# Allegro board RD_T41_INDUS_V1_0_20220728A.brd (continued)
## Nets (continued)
BT_UART_CTS/PIR_PWR_EN_IOT: J14.7 R218.2 R220.2
BT_UART_RTS/LED_R_IOT: J14.6 R223.2 R225.2
BT_UART_RXD/USART2_TX_IOT: J14.8 R213.2 R215.2
BT_UART_TXD/USB_DET_IOT: J14.5 R187.2 R188.2
CHARG_DET_N_IOT: J14.4 R8.1 U1.9(STATS)
CLK_CTRL: R199.2 R200.1 U19.12(RXD[3]/CLK_CTL)
CODEC_AVDD: C61.1 C62.1 FB8.2 U7.R1(CODEC_AVDD)
CSI_CLKN_DVP_D4: R110.1 R124.1 TP26.1 U7.M2(CSI_CLKN_DVP_D4)
CSI_CLKP_DVP_D5: R108.1 R109.1 TP25.1 U7.L3(CSI_CLKP_DVP_D5)
CSI_DATAN0_DVP_D0: R102.1 R103.1 TP21.1 U7.L2(CSI_DATAN0_DVP_D0)
CSI_DATAN1_DVP_D2: R106.1 R107.1 TP24.1 U7.N1(CSI_DATAN1_DVP_D2)
CSI_DATAP0_DVP_D1: R100.1 R101.1 TP18.1 U7.L1(CSI_DATAP0_DVP_D1)
CSI_DATAP1_DVP_D3: R104.1 R105.1 TP23.1 U7.M3(CSI_DATAP1_DVP_D3)
CSI_VCC08: C146.1 C147.1 FB9.1 U7.N2(CSI_VCCA08)
CSI_VCC18: C144.1 C145.1 FB10.1 U7.K3(CSI_VCCA18)
DDR_VREF: C42.2 C43.1 R118.1 R119.2 U7.E5(DDR_VREF)
DDRPLL_VCCA: C133.1 C134.1 FB2.1 U7.B8(DDRPLL_VCCA)
DDRVDD: C37.1 C38.1 C39.1 C40.1 C41.1 C42.1 C44.1 C58.1 C129.1 C130.1 C131.1 C132.1 R30.1 R118.2 U7.E6(VDDMEM1) U7.E7(VDDMEM2) U7.E8(VDDMEM3) U7.E9(VDDMEM4) U7.E10(VDDMEM5) U7.E11(VDDMEM6) U7.E12(VDDMEM7) U7.F5(DDRVDD1) U7.F6(DDRVDD2) U7.F7(DDRVDD3) U7.F8(DDRVDD4) U7.F9(DDRVDD5) U7.F10(DDRVDD6) U7.F11(DDRVDD7) U7.F12(DDRVDD8)
DVP_3V3: J10.1 J10.2 R99.1
DVP_5V: J10.34 J10.35 J10.36 R127.1
DVP_D0: J10.11 R103.2
DVP_D1: J10.12 R101.2
DVP_D2: J10.13 R107.2
DVP_D3: J10.14 R105.2
DVP_D4: J10.16 R124.2
DVP_D5: J10.17 R109.2
DVP_D6: J10.18 U7.H2(SD0_DVP_D6_PA06)
DVP_D7: J10.19 U7.H3(SD1_DVP_D7_PA07)
DVP_D8: J10.21 U7.G1(SD2_DVP_D8_PA08)
DVP_D9: J10.22 U7.G2(SD3_DVP_D9_PA09)
DVP_D10: J10.23 U7.G3(SD4_DVP_D10_PA10)
DVP_D11: J10.24 U7.F2(SD5_DVP_D11_PA11)
DVP_HSYNC: J10.8 TP20.1 U7.J2(CS2_DVP_HSYNC_PA16)
DVP_MCLK_PA15: J10.28 R126.2 TP10.1
DVP_PCLK: J10.26 TP19.1 U7.F3(SA0_DVP_PCLK__PA14)
DVP_VSYNC: J10.9 TP22.1 U7.J3(RD_DVP_VSYNC_PA17)
EMMC_3V3: C87.1 C88.1 FB1.2 U11.E6(VCC_1) U11.F5(VCC_2) U11.J10(VCC_3) U11.K9(VCC_4)
EMMC_D4: R74.2 U11.B3(DAT4)
EMMC_D5: R75.2 U11.B4(DAT5)
EMMC_D6: R76.2 U11.B5(DAT6)
EMMC_D7: R77.2 U11.B6(DAT7)
EMMC_DS: TP33.1 U11.H5(DS)
EMMC_MSC0_CLK: C91.1 R86.2 U11.M6(CLK)
EMMC_MSC0_CMD: R78.2 R84.2 U11.M5(CMD)
EMMC_MSC0_D0: R70.2 R131.2 U11.A3(DAT0)
EMMC_MSC0_D1: R71.2 R133.2 U11.A4(DAT1)
EMMC_MSC0_D2: R72.2 R135.2 U11.A5(DAT2)
EMMC_MSC0_D3: R73.2 R137.2 U11.B2(DAT3)
EMMC_RST_PB21: C92.1 R79.1 U7.C17(MSC1_D2_TMS_PB21) U11.K5(RSTN)
EMMC_VDDI: C93.1 U11.C2(VDDI)
EXCLKI: C66.2 R41.2 U7.C1(EXCLK_XIN) Y1.1
EXCLKO: C67.2 R41.1 U7.D2(EXCLK_XOUT) Y1.3
GMAC_MDC: R177.2 U19.22(MDC)
GMAC_MDIO: R178.2 R189.2 U19.23(MDIO)
GMAC_NRST_PB28: C151.1 R207.2 U7.A11(DMIC_CLK_SMB2_SCK_PB28) U19.21(RESET_N)
GMAC_PHY_CLK: R175.2 U19.31(XTAL_IN)
GMAC_RXD0: R195.1 U7.U13(GMAC_RXD0_PWM6_PB15)
GMAC_RXD1: R192.2 R193.1 R198.1 U7.R12(GMAC_RXD1_PWM7_PB16)
GMAC_RXDV: R191.1 U7.U9(GMAC_RXDV_PWM3_PB09)
GMAC_TXCLK: R190.1 U7.T12(GMAC_TXCLK_PB06)
GMAC_TXD0: R179.2 U19.16(TXD[0])
GMAC_TXD1: R180.2 U19.17(TXD[1])
GMAC_TXEN: R176.2 U19.20(TXEN)
HPOUT: C76.2 U7.T1(HPOUTL)
I2C0_MIPI_DVP_SCK: J10.3 J11.20 TP29.1 U7.J4(SD7_SMB0_SCK_PA13)
I2C0_MIPI_DVP_SDA: J10.6 J11.19 TP28.1 U7.J1(SD6_SMB0_SDA_PA12)
I2C1_SCK_PB26: R46.2 R152.1 R184.1 U9.7(SCL) U21.6(SCL)
I2C1_SDA_PB25: R40.2 R140.1 R182.1 U9.8(SDA) U21.5(SDA)
IRLED_EN_N_PB19: C102.2 Q8.1(GATE) R165.1 U7.D16(MSC1_CMD_PB19)
KEY1_PB30: R89.1 SW1.2 U7.C12(DMIC_DAT1_UART4_RXD_PB30)
KEY_IOT_N: C95.2 D10.2(CATHODE) J9.18 R90.2 SW2.1
LDR0: C125.1 R92.1 R113.1 U7.P15(SADC_VIN0)
LED_G: R94.1 R181.1
LED_R_IOT: R95.1 R225.1
MCU_PWR: R8.2 R47.1 R54.1 R90.1 R93.1 R186.2
MICBIAS: C141.1 C142.1 R83.2 U7.P3(MICBIAS)
MICNL: C65.2 C78.1 D15.2(CATHODE) J7.1 R69.1
MICPL: C64.2 C78.2 D9.2(CATHODE) J7.2 R80.2
MIPI1_2LANE_3V3: J11.30 R129.2
MIPI1_2LANE_5V: J11.28 J11.29 R128.2
MIPI_DVP_IRCUTN_PB18: J10.31 J11.25 U7.E17(MSC1_D1_PB18)
MIPI_DVP_IRCUTP_PB17: J10.32 J11.24 U7.E16(MSC1_D0_PB17)
MIPI_DVP_MCLK: R38.1 R125.1 R126.1 TP27.1
MIPI_DVP_PWDN_PA19: J10.25 J11.26 R143.1 TP31.1
MIPI_DVP_RESET: J10.33 J11.18 TP30.1 U7.E3(SA2_PA18)
MIPI_MCLK_PA15: J11.22 R125.2 TP32.1
MIPI_RX_2LANE_CLKN0: J11.2 R110.2
MIPI_RX_2LANE_CLKP0: J11.3 R108.2
MIPI_RX_2LANE_DN0: J11.5 R102.2
MIPI_RX_2LANE_DN1: J11.8 R106.2
MIPI_RX_2LANE_DP0: J11.6 R100.2
MIPI_RX_2LANE_DP1: J11.9 R104.2
MSC0_CLK: R39.2 R85.1 R86.1
MSC0_CMD: R82.1 R84.1 U7.G17(MSC0_CMD_PB05)
MSC0_D0: R87.1 R131.1 U7.H16(MSC0_D0_PB00)
MSC0_D1: R132.1 R133.1 U7.J15(MSC0_D1_PB01)
MSC0_D2: R134.1 R135.1 U7.G15(MSC0_D2_PB02)
MSC0_D3: R136.1 R137.1 U7.G16(MSC0_D3_PB03)
NTC: R9.1 R11.2 TP3.1 U1.7(NTC)
OSC32_XI: C71.2 R52.2 U7.M16(OSC32_XI) Y3.2
OSC32_XO: C72.2 R52.1 U7.M15(OSC32_XO) Y3.1
OU_PWR_EN_PC18: D12.2 R233.1 U7.B5(SSI_SLV_DR_I2S_SDTI_PC18)
PHY_LED0: R202.2 R203.1 R211.2 U19.24(LED0/PHYAD[0])
PHY_LED1: R205.2 R206.1 R217.2 U19.25(LED1/PHYAD[1])
PIR_3V3: C123.1 C124.1 C127.1 C196.1 D18.1(ANODE) R227.2 R228.1 R258.2 R265.2 TP11.1 U15.5(VOUT) U24.4 U25.3(VDD)
PIR_H_IOT: J14.11 Q6.1(GATE) U24.1
PIR_IOT: R230.1 R257.2 U25.4(REL)
PIR_L_IOT: J14.13 Q7.1(GATE) U24.7
PIR_PWR_EN_IOT: C126.1 D18.2(CATHODE) R220.1 U15.3(EN)
PLL_AVDD18: C59.1 C60.1 FB3.1 U7.D3(PLL_AVDD)
POR_CTRL: R121.2 R122.2 U7.K16(POR_CTL)
PWR_ON_PC16: J14.2 U7.A3(SSI_SLV_CE0_I2S_DAC_LRCK_PC16)
PWRON: TP12.1 U7.K15(PWRON)
RMII_MDCK: R177.1 U7.R10(GMAC_MDCK_SMB2_SDA_PB10)
RMII_MDIO: R178.1 U7.T10(GMAC_MDIO_SMB2_SCK_PB11)
RMII_PHY_CLK: R175.1 U7.T9(GMAC_PHY_CLK_PB07)
RMII_TX0: R179.1 U7.R11(GMAC_TXD0_PWM4_PB13)
RMII_TX1: R180.1 U7.T11(GMAC_TXD1_PWM5_PB14)
RMII_TXEN: R176.1 U7.U11(GMAC_TXEN_PWM2_PB08)
RST_OUT: TP14.1 U7.J16(RST_OUT)
RTC_0V8: C99.1 C143.1 TP34.1 U7.L15(VDD_RTC) U13.5(VOUT)
RTC_1V8: C94.1 C98.1 C169.1 R97.2 R121.1 R142.1 TP36.1 U7.L17(VDDIO_RTC) U12.5(VOUT) U13.1(VIN)
RTC_IRQ_N_PB29: R153.1 U7.B12(DMIC_DAT0_UART4_TXD_PB29) U21.3(INT)
RX+: J13.3(CON_PIN[2]) U20.14(TX-/RX-)
RX-: J13.6(CON_PIN[5]) U20.16(TX+/RX+)
RX_N1: U19.6(TRXN1) U20.1(TD+/RD+)
RX_P1: U19.5(TRXP1) U20.3(TD-/RD-)
RXDV: R196.2 R197.1 U19.8(RXDV)
SD0_CD_N_PB27: J6.9(CD) R88.1 U7.B11(DRV_VBUS_SMB2_SDA_PB27)
SD0_MSC0_CLK: J6.5(CLK) R85.2
SD0_MSC0_CMD: J6.3(CMD) R61.2 R82.2
SD0_MSC0_D0: J6.7(DAT0) R62.2 R87.2
SD0_MSC0_D1: J6.8(DAT1) R63.2 R132.2
SD0_MSC0_D2: J6.1(DAT2) R64.2 R134.2
SD0_MSC0_D3: J6.2(DAT3) R65.2 R136.2
SD_PWR_EN_N_PB20: C82.2 Q3.1(GATE) R66.2 U7.E15(MSC1_CLK_TCK_PB20)
SENS1: C204.1 Q6.2(SOURCE) Q7.2(SOURCE) R265.1 R267.2 U25.2(SENS)
SFC1_CS_N: R123.1 U7.R7(SFC1_CE_PA29) U18.1(C\S\)
SFC1_SCLK: U7.T8(SFC1_CLK_PA22) U18.6(SCLK)
SFC1_SIO0: U7.R8(SFC1_DT_IO0_PA20) U18.5(SI/SIO0)
SFC1_SIO1: U7.T7(SFC1_DR_IO1_PA21) U18.2(SO/SIO1)
SFC1_SIO2: U7.U7(SFC1_WP_IO2_PA30) U18.3(W\P\/SIO2)
SFC1_SIO3: U7.R9(SFC1_HOLD_IO3_PA31) U18.7(R\E\S\E\T\/SIO3)
SFC_CS_N: R44.1 U7.T4(SFC0_CE_PA28) U8.1(C\S\)
SFC_SCLK: R43.1 U8.6(SCLK)
SFC_SIO0: U7.U5(SFC0_DT_IO0_PA23) U8.5(SI/SIO0)
SFC_SIO1: U7.R5(SFC0_DR_IO1_PA24) U8.2(SO/SIO1)
SFC_SIO2: U7.T5(SFC0_WP_IO2_PA26) U8.3(W\P\/SIO2)
SFC_SIO3: U7.T6(SFC0_HOLD_IO3_PA25) U8.7(R\E\S\E\T\/SIO3)
SLCD_BLEN: R183.1 R212.1 U23.15(EN1) U23.16(EN2)
SLCD_BT656_D0: R130.1 R144.1 U7.A15(SLCD_D0_UART3_TXD_PD00)
SLCD_BT656_D1: R145.1 R146.1 U7.B15(SLCD_D1_UART3_RXD_PD01)
SLCD_BT656_D2: R149.1 R150.1 U7.A16(SLCD_D2_UART4_TXD_PD02)
SLCD_BT656_D3: R154.1 R155.1 U7.C15(SLCD_D3_UART4_RXD_PD03)
SLCD_BT656_D4: R156.1 R158.1 U7.A17(SLCD_D4_UART5_TXD_PD04)
SLCD_BT656_D5: R160.1 R161.1 U7.B16(SLCD_D5_UART5_RXD_PD05)
SLCD_BT656_D6: R162.1 R163.1 U7.B17(SLCD_D6_SMB1_SDA_PD06)
SLCD_BT656_D7: R164.1 R166.1 U7.C16(SLCD_D7_SMB1_SCK_PD07)
SLCD_CS: R171.1 U7.B13(SLCD_CS_PWM5_PD10)
SLCD_CS_PD10: J15.7(CS) R171.2
SLCD_D0_PD00: J15.23(DB10) R130.2
SLCD_D1_PD01: J15.24(DB11) R145.2
SLCD_D2_PD02: J15.25(DB12) R149.2
SLCD_D3_PD03: J15.26(DB13) R154.2
SLCD_D4_PD04: J15.27(DB14) R156.2
SLCD_D5_PD05: J15.28(DB15) R160.2
SLCD_D6_PD06: J15.29(DB16) R162.2
SLCD_D7_PD07: J15.30(DB17) R164.2
SLCD_DC: R172.1 U7.C13(SLCD_DC_PWM6_PD11)
SLCD_DC_PD11: J15.8(RS) R172.2
SLCD_IOVDD: C105.1 C106.1 J15.32(IOVCC) R147.2
SLCD_LEDA: C185.2 J15.16(LED-A) U23.8(VOUT)
SLCD_LEDK: J15.17(LED1) J15.18(LED2) J15.19(LED3) J15.20(LED4) U23.4(D3) U23.5(D2) U23.6(D1)
SLCD_RDY: R174.1 U7.C14(SLCD_RDY_PWM7_PD12)
SLCD_RDY_PD12: J15.10(RD) R157.1 R174.2
SLCD_RST_PD09: J15.31(RESET) R170.2
SLCD_TE: R170.1 U7.A13(SLCD_TE_PWM4_PD09)
SLCD_VCI: C179.1 C180.1 J15.33(VCI) R148.2
SLCD_WR_BT656_PCLK: R168.1 R169.1 U7.B14(SLCD_WR_PD08)
SLCD_WR_PD08: J15.9(WR) R168.2
SOC_0V8: C46.1 C47.1 C48.1 C49.1 C50.1 C51.1 C52.1 C53.1 C54.1 C55.1 C56.1 C57.1 FB4.1 FB9.2 R31.1 U7.H5(VDD1) U7.H6(VDD2) U7.H7(VDD3) U7.H8(VDD4) U7.H9(VDD5) U7.H10(VDD6) U7.H11(VDD7) U7.H12(VDD8) U7.H13(VDD9) U7.J5(VDD10) U7.J13(VDD11) U7.K5(VDD12) U7.K13(VDD13) U7.L5(VDD14) U7.M5(VDD15) U7.M6(VDD16) U7.N6(VDD17) U7.N7(VDD18) U7.N8(VDD19) U7.N9(VDD20) U7.N10(VDD21)
SOC_1V8: C63.1 C174.1 C175.1 C176.1 C177.1 FB2.2 FB3.2 FB5.1 FB7.1 FB8.1 FB10.2 R20.1 R185.1 U7.K2(VDDIO18_2) U7.N11(VDDIO18_1)
SOC_3V3: C170.1 C171.1 FB6.1 J4.1 R19.1 R40.1 R42.2 R45.2 R46.1 R138.1 U7.J14(VDDIO1_2) U7.P9(VDDIO1_1)
SOC_BT_RST_N/PIR_IOT: J14.16 R229.2 R230.2
SOC_BT_RST_PC17: R229.1 U7.B3(SSI_SLV_DT_I2S_SDTO_PC17)
SOC_PWR_EN_IOT: D12.1 J9.17
SOC_WIFI_OOB_PC15: J14.1 U7.B4(SSI_SLV_CLK_I2S_DAC_BCLK_PC15)
SPEAK_EN: R58.1 U7.B10(GPIO_PB31) U10.1(/SD)
TEST_TE: TP16.1 U7.L13(TEST_TE)
TRST_: TP15.1 U7.D14(TRST_)
TX+: J13.1(CON_PIN[0]) U20.9(RX-/TX-)
TX-: J13.2(CON_PIN[1]) U20.11(RX+/TX+)
TX_N0: U19.4(TRXN0) U20.6(RD+/TD+)
TX_P0: U19.3(TRXP0) U20.8(RD-/TD-)
UART1_RXD: R42.1 R48.2 U7.F16(UART1_RXD_PB24)
UART1_TXD: R45.1 R51.2 U7.F15(UART1_TXD_PB23)
UART2_RXD_PC14: R215.1 U7.C7(I2S_ADC_LRCK_PC14)
UART2_TXD_PC13: J14.12 U7.B7(I2S_ADC_BCLK_PC13)
USB_AVD08: C135.1 C136.1 FB4.2 U7.R4(USB_AVD08)
USB_AVD18: C137.1 C138.1 FB5.2 U7.T3(USB_AVD18)
USB_AVD33: C139.1 C140.1 FB6.2 U7.R3(USB_AVD33)
USB_DET_IOT: C9.1 R10.1 R12.2 R188.1
USB_DM0: D2.2(CATHODE) J2.2(D-) U7.U1(USB0PN)
USB_DP0: D1.2(CATHODE) J2.3(D+) U7.T2(USB0PP)
USB_ID: R55.1 U7.U2(USB0ID)
USB_VBUS: R24.1 R27.1 U7.U3(VBUS)
VCM: C68.1 C69.1 U7.R2(VCM)
VOUT: C198.1 R255.1 R259.2 U16.2(VOUT)
WIFI_IO: C114.1 J14.17 R186.1
WIFI_MSC1_CLK_PC02: J9.10 U7.A1(MSC1_CLK_PC02)
WIFI_MSC1_CMD_PC03: J9.7 R246.2 U7.C3(MSC1_CMD_PC03)
WIFI_MSC1_D0_PC04: J9.11 R247.2 U7.B2(MSC1_D0_PC04)
WIFI_MSC1_D1_PC05: J9.14 R248.2 U7.A2(MSC1_D1_PC05)
WIFI_MSC1_D2_PC06: J9.5 R249.2 U7.C2(MSC1_D2_PC06)
WIFI_MSC1_D3_PC07: J9.6 R250.2 U7.B1(MSC1_D3_PC07)
WIFI_VBAT: C111.1 C112.1 C113.1 J9.1 J9.2 R13.1 TP4.1
WKUP: TP13.1 U7.J17(WKUP_PD31)
N6875993: D7.2(CATHODE) J5.1 U10.8(VO-)
N6876005: D6.2(CATHODE) J5.2 U10.5(VO+)
N6876073: C77.1 R56.1 R57.1 U10.6(VDD)
N6876131: R60.1 U10.4(-IN)
N6876183: C76.1 R60.2
N6876193: C75.1 R59.2
N7727802: D11.3 R95.2
N7727853: D11.2 R94.2
N16597671: R59.1 U10.3(+IN)
N16605475: R6.2 U1.11(ISET1)
N16605479: R7.2 U1.12(ISET2)
N16605539: L1.1 U1.3(SW_0) U1.4(SW_1)
N16605973: R4.1 R5.1 U1.13(USB_DET)
N16607200: J1.3 R1.2
N16626294: R15.1 U2.4(EN)
N16626314: C10.1 C11.1 R14.2 R15.2 U2.5(VIN)
N16626426: R16.1 R17.2 U2.3(FB)
N16626534: C28.1 C29.1 C34.1 L5.2 R30.2 R33.2 TP8.1 U5.6(OUT)
N16626558: C34.2 R33.1 R36.2 U5.1(FB)
N16626586: C24.2 R25.1 R28.2 U3.1(FB)
N16626718: L5.1 U5.4(SW)
N16626738: L3.1 U3.4(SW)
N16627048: C206.1 R32.2 U5.5(EN)
N16627266: L2.1 U2.1(SW)
N16627350: C96.1 R22.2 U3.5(EN)
N16676856: C25.2 R23.1 R29.2 U4.1(FB)
N16676932: L4.1 U4.4(SW)
N16677062: C205.1 R26.2 U4.5(EN)
N16732442: R43.2 U7.R6(SFC0_CLK_PA27)
N16973565: R116.2 U7.F13(DDR_ZQ)
N16973568: R117.2 U7.D9(RZQ)
N16979467: D4.2(CATHODE) J4.4 R51.1
N16979485: D5.2(CATHODE) J4.3 R48.1
N16981740: C64.1 U7.N3(MICPL)
N16981743: C65.1 U7.P2(MICNL)
N16981952: R120.2 U7.D4(EFUSE_AVDD)
N16985653: R38.2 U7.E1(SA1_DVP_MCLK_PA15)
N16990829: C85.1 R81.1 R83.1
N16990879: C79.2 R80.1 R81.2
N16990962: C79.1 R67.1 R69.2
N16994187: R142.2 U13.3(EN)
N16994244: C100.1 U13.4(BP/FB)
N16994305: C97.1 U12.4(BP/FB)
N16994361: R141.2 U12.3(EN)
N16994635: R143.2 U7.E2(WAIT_PA19)
N17002165: R191.2 U19.26(CRS/CRS_DV)
N17002179: R195.2 U19.9(RXD[0])
N17002181: R198.2 U19.10(RXD[1])
N17002261: R209.1 U19.30(NC)
N17002291: R204.2 U19.32(XTAL_OUT)
N17002321: R190.2 U19.15(TXC)
N17002359: C118.1 C119.1 U19.2(AVDDL_REG)
N17002395: C149.1 C150.1 U19.29(DVDDL_REG)
N17002469: R201.2 U19.28(RXER)
N17002544: R194.1 U19.1(PBIAS)
N17002574: C156.2 U20.7(CT2)
N17002587: D17.1 R221.2 U20.10(CT3) U20.13(MCT) U20.15(CT4)
N17002598: C155.2 U20.5(CT)
N17002608: C154.2 U20.2(CT1)
N17002683: J13.11(CON_PIN[10]) R211.1
N17002690: J13.13(CON_PIN[12]) R217.1
N17002738: C157.2 R221.1
N17006161: R98.1 R139.1 R246.1 R247.1 R248.1 R249.1 R250.1
N17009042: Q4.2(EMITTER) R92.2
N17009044: Q5.3(DRAIN) R113.2 R115.2
N17009046: Q5.1(GATE) R114.1
N17009089: C121.1 C122.1 R111.2 U15.1(VIN)
N17009287: Q6.3(DRAIN) R268.2
N17009319: Q7.3(DRAIN) R269.2
N17009402: C201.1 R258.1 R261.1 R262.2 U24.10
N17009422: R253.1 R261.2 R263.2
N17009484: C199.1 R255.2 U24.12
N17009506: C199.2 C200.1 R260.1 R264.2 U24.13
N17009512: C197.1 C200.2 R260.2 U24.14
N17009562: C202.1 R264.1
N17009566: C197.2 R256.2
N17009576: C195.1 R254.1 R256.1 U24.9
N17009610: C195.2 R254.2 R257.1 U24.3 U24.6 U24.8
N17009693: C203.1 R263.1 R266.2 U24.5
N17009695: C194.1 R227.1 R253.2 U24.2
N17009885: C188.1 C189.1 C190.1 C191.1 C192.1 C193.1 R252.2 U16.1(VCC)
N17009958: C128.1 C187.1 R228.2 R252.1
N17058437: R39.1 U7.H15(MSC0_CLK_PB04)
N17123098: C36.1 R49.1 U9.2(CELL)
N17123136: R53.1 U9.6(QSTRT)
N17123180: C45.1 R50.1 U9.3(VDD)
N17123378: R181.2 R182.2 U7.C11(SMB1_SDA_UART3_TXD_PB25)
N17123417: R183.2 R184.2 U7.C10(SMB1_SCK_UART3_RXD_PB26)
N17141430: C15.2 J3.1 Q1.1(GATE) Q2.3(COLLECTOR) R21.2
N17141450: D12.3 R231.2
N17141452: C15.1 Q1.2(SOURCE) R18.2 R21.1
N17141508: Q2.1(BASE) R231.1 R232.2
N17141576: D13.1(ANODE) R234.2
N17211450: C158.2 U21.1(OSCI) Y2.2
N17211478: C159.2 U21.2(OSC0) Y2.1
N17217380: C183.2 U23.10(C1+)
N17217382: C183.1 U23.11(C1-)
N17217384: C182.1 U23.12(C2-)
N17217386: C182.2 U23.9(C2+)
N17217517: R214.1 U23.1(ISET)
N17219479: C107.1 D14.1(ANODE) Q8.3(DRAIN) R167.1
N17219520: D14.2(CATHODE) D16.1(ANODE)
N17219530: D16.2(CATHODE) R159.1
N17242896: C32.1 C33.1 C35.1 L6.2 R31.2 R35.2 TP9.1 U14.6(OUT)
N17242898: C35.2 R35.1 R37.2 U14.1(FB)
N17242946: L6.1 U14.4(SW)
N17243021: C108.1 R34.2 U14.5(EN)
N17251040: R208.1 U6.4(EN)
N17251042: C164.1 C165.1 R173.2 R208.2 U6.5(VIN)
N17251086: R91.1 R96.1 U6.3(FB)
N17251195: L8.1 U6.1(SW)
N170100671: Q5.2(SOURCE) R226.2

Pads without a net: D11 1; J2 4; J10 4 5 30; J11 11 12 14 15 17; J13 4 5 7 8; J15 11 12 13 14 15 21; U2 2; U6 2; U7 A7 C8 L16 N15 P14 P16 R13 R14 R15 R16 R17 T13 T14 T15 T16 T17 U15 U16 U17; U9 9; U10 2; U11 A1 A2 A7 A8 A9 A10 A11 A12 A13 A14 B1 B7 B8 B9 B10 B11 B12 B13 B14 C1 C3 C5 C7 C8 C9 C10 C11 C12 C13 C14 D1 D2 D3 D4 D12 D13 D14 E1 E2 E3 E5 E8 E9 E10 E12 E13 E14 F1 F2 F3 F10 F12 F13 F14 G1 G2 G3 G10 G12 G13 G14 H1 H2 H3 H12 H13 H14 J1 J2 J3 J12 J13 J14 K1 K2 K3 K6 K7 K10 K12 K13 K14 L1 L2 L3 L12 L13 L14 M1 M2 M3 M7 M8 M9 M10 M11 M12 M13 M14 N1 N3 N6 N7 N8 N9 N10 N11 N12 N13 N14 P1 P2 P7 P8 P9 P10 P11 P12 P13 P14; U15 4; U19 11 13 18 19 27; U20 4 12; U21 7; U23 2 3

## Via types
v1: diameter 0.406, hole 0.203, TOP to BOTTOM, 1508 vias

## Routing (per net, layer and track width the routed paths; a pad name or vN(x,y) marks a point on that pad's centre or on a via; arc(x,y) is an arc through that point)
1V8: length 57
  TOP w0.254: v1(41.12,41.52) 43.57,41.52 43.87,41.22 45.29,41.22 46.68,39.83 R55.2 ; R139.2 68.01,46.78 v1(67.03,45.8)
  TOP w0.508: v1(32.64,42.85) 33.97,42.85 35.31,41.52 v1(41.12,41.52)
  BOTTOM w0.254: 32.59,41.88 32.59,41.41 32.41,41.22 28.34,41.22 C25.1 26.98,41.47 R23.2
  BOTTOM w0.381: v1(67.03,45.8) 63.56,45.8 62.35,47.01 45.64,47.01 41.12,42.49 v1(41.12,41.52)
3V3: length 147.7
  TOP w0.203: R205.1 v1(37.68,24.62)
  TOP w0.254: U8.8 33.57,28.73 C70.2 v1(33.58,28.06) ; R44.2 31.77,39.64 v1(31.69,39.56) ; v1(77.97,42.96) 80.4,42.96 81.91,44.47 99.49,44.47 R270.2 ; U19.14 v1(35.51,15.53) 35.72,15.32 R199.1 ; v1(68.94,47.75) R98.2 ; R207.1 v1(39.75,20.46) ; R157.2 v1(90.72,20.74) ; v1(75.59,35.68) R140.2 74.93,35.67 R153.2 ; v1(40.63,22.49) R202.1 R189.1 ; R271.2 v1(68.11,37.66) ; R89.2 86.17,30.11 ; R152.2 v1(73.85,35.1)
  TOP w0.381: R151.1 v1(90.16,28.12)
  TOP w0.508: Q4.1 82.72,90.43 80.49,90.43 C120.1 78.16,90.55 71.2,90.55 R112.2 69.43,89.3 60.03,79.9 32.38,79.9 ; v1(23.63,65.21) 15.42,73.42 R57.2
  BOTTOM w0.254: R123.2 31.49,34.08 ; v1(73.85,35.1) 73.85,37.21 ; R25.2 26.65,48.04 C24.1 27.99,47.72 31.62,47.72 31.92,48.02 ; 31.36,80.46 R165.2 32.2,79.73 C102.1 ; v1(75.59,35.68) 75.59,37.11
  BOTTOM w0.381: 57.98,7.99 60.12,5.85 FB1.1
  BOTTOM w0.508: v1(37.18,65.21) v1(23.63,65.21)
  vias: v1(32.34,48.55) v1(32.75,81.45) v1(32.71,80.57) v1(32.92,48.54) v1(37.12,58.5) v1(38,58.48) v1(40.17,48.99) v1(40.38,48.53) v1(78,40.92) v1(78.1,40.31) v1(88.03,30.45) v1(88.5,10.94) v1(88.95,30.44) v1(89.57,10.95)
AVDD33: length 0.7
  TOP w0.254: U19.7 v1(31.56,17.55)
GND: length 197
  TOP w0.081: 62.82,10.27 62.77,10.32 62.77,10.81 ; 63.27,10.88 63.27,10.32 63.22,10.27
  TOP w0.102: 51.1,29.53 51,29.64 ; 51.1,29.53 51.1,29.14 ; 51.1,29.53 51.1,29.64 ; 51,29.64 51.1,29.64 51.1,29.64 ; 51,29.64 51,29.64 ; v1(51.1,30.93) v1(51.1,30.28) 51.1,29.74 ; v1(51.1,30.93) v1(50.45,30.93) v1(50.45,30.28) 50.45,29.73 ; v1(51.1,30.93) 51.68,30.93 ; 50.35,29.64 50.38,29.64 ; 50.35,29.64 50.45,29.73 ; 50.35,29.64 49.95,29.64 ; 50.38,29.64 50.45,29.57 ; 50.38,29.64 50.52,29.64 ; 51,29.64 50.55,29.64 ; 51,29.64 51.1,29.74 ; 50.55,29.64 50.45,29.73 ; 50.55,29.64 50.52,29.64 ; 51.77,30.93 51.88,30.93 ; 51.77,30.93 51.77,31.02 ; 51.77,30.93 51.68,30.93 ; 51.88,30.93 52.25,30.93 ; 51.88,30.93 51.77,31.04 ; 51.1,29.74 51.1,29.64 ; 50.45,29.73 50.45,29.57 ; 51.77,31.04 51.77,31.48 ; 51.77,31.04 51.77,31.02 ; 50.51,31.57 51.7,31.57 ; 50.45,29.57 50.45,29.12 ; 50.45,29.57 50.52,29.64 ; 51.68,30.93 51.77,31.02
  TOP w0.203: C151.2 39.12,20.19 v1(39.12,20.45) ; v1(23.01,85.31) D9.1 v1(22.23,86) ; 64.52,7.07 64.47,7.07 64.09,6.69 v1(64.09,6.41) ; U7.K6 v1(54.35,36.13) U7.K7 ; v1(51.37,54.35) J11.10 v1(51.37,56.09) ; 23.11,79.85 C85.2 23.11,81.21 ; U11.J5 65.22,8.37 65.22,8.07 v1(65.23,8.06) ; U7.L6 v1(53.7,36.13) U7.L7 ; D5.1 v1(77.19,7.96) ; D5.1 v1(76.46,7.28) ; D5.1 77.19,6.73 v1(77.39,6.54) ; v1(80.56,7.96) D4.1 v1(81.29,7.28) ; U7.L8 v1(53.7,34.83) U7.L9 ; C9.2 88.27,54.15 R12.1 ; 65.53,6.07 65.76,5.83 v1(65.76,5.67) ; J11.7 v1(52.87,56.9) ; R204.1 v1(32.73,24.66) ; v1(18.86,85.93) D15.1 v1(18.07,85.31) ; v1(62.03,7.83) 62.29,7.83 U11.P6 62.54,8.07 63.02,8.55 63.02,8.57 ; v1(77.95,89.91) 77.95,89.72 C120.2 ; v1(67.41,7.33) 67.17,7.57 67.02,7.57 ; U7.J9 v1(55,34.83) U7.J8 ; R58.2 v1(9.45,75.83) ; v1(48.37,56.17) J11.16 v1(48.37,54.3) ; C95.1 v1(96.18,62.33) ; U7.J7 v1(55,36.13) U7.J6 ; U7.J10 v1(55,33.53) U7.J11 ; U7.N12 v1(52.4,32.22) U7.N13 ; U7.K10 v1(54.35,33.53) U7.K11 ; v1(65.86,8.14) 66.02,8.3 66.02,8.57 ; U7.K9 v1(54.35,34.83) U7.K8 ; U7.M13 v1(53.05,32.22) U7.M12 ; R272.1 65.37,34.92 v1(65.37,34.65) ; U7.C9 v1(59.55,34.83) ; U11.P4 v1(62.03,9.07) ; R206.2 v1(36.79,24.62) ; v1(92.48,45.53) 92.47,45.54 C114.2 91.18,45.54 v1(91,45.72) ; J11.1 v1(55.87,57.05) ; D10.1 v1(97.16,62.21) ; U11.C4 v1(67.52,8.57) ; U7.L10 v1(53.7,33.53) U7.L11 ; 63.27,10.88 63.04,11.11 v1(63.02,11.11) 62.77,10.87 62.77,10.81 ; 63.22,10.27 63.02,10.07 U11.N2 62.82,10.27 ; R200.2 R193.2 v1(33.86,15.31) ; J11.13 v1(49.87,57.03) ; R194.2 v1(31.68,24.68) ; J11.4 v1(54.37,56.14) ; R226.1 v1(69.94,86.69) ; U8.4 v1(29.76,36.18) ; C125.2 v1(78.15,87.34) ; R201.1 v1(34.3,24.02) ; R115.1 v1(75.71,87.35)
  TOP w0.254: v1(88.59,53.53) 88.27,53.85 R12.1 ; U7.G8 v1(56.95,35.48) U7.G7 ; U7.G9 v1(56.95,34.18) U7.G10 ; U7.G5 v1(56.95,36.78) U7.G6 ; U7.G12 v1(56.95,32.87) U7.G11 ; C70.1 v1(31.94,28.72) ; J4.2 v1(77.39,6.54) ; R203.2 v1(40.63,23.38) ; U7.N5 v1(52.4,37.43)
  TOP w0.305: U7.G13 56.63,31.9 v1(56.95,31.58) ; v1(45.87,58.88) J11.21 v1(45.87,56.98) ; v1(46.42,74.05) J10.20 v1(46.42,75.99) ; v1(44.87,56.98) J11.23 v1(44.87,58.88) ; J10.15 v1(43.92,73.29) ; v1(42.87,56.98) J11.27 v1(42.87,58.88) ; v1(50.92,71.35) J10.29 v1(50.92,73.29) ; v1(10.29,84.77) 10.14,84.61 U10.7 v1(10.14,82.46) ; v1(45.18,13.7) J6.6 v1(45.18,16.22) ; v1(49.92,73.29) J10.27 v1(49.92,71.35) ; v1(41.42,75.99) J10.10 v1(41.42,74.05) ; U7.P4 v1(52.4,37.43) ; J10.7 v1(39.92,73.29)
  TOP w0.33: v1(78.4,18.04) C98.2 77.82,17.83 v1(77.44,18.21) U13.2 75.78,19.87 v1(75.7,19.87) ; C99.2 v1(71.53,20.5)
  TOP w0.381: v1(19.01,80.79) R67.2 v1(18.29,81.43) ; R27.2 44.22,39.57 v1(43.96,39.3) ; v1(12.12,80.83) C77.2 v1(12.88,80.07)
  TOP w0.508: J13.14 14.71,10.75 14.71,8.28 ; J13.10 8.35,7.7 ; 12.59,28.57 12.59,24.3 J13.12 ; J13.9 8.35,28.49
  BOTTOM w0.203: v1(65.76,5.67) 65.76,5.49 C87.2 ; C13.2 v1(87.35,43.67) ; R120.1 59.51,40.29 v1(59.53,40.32) ; C80.2 v1(46.74,5.68) ; v1(24.28,43.59) 24.28,43.84 C20.2 23.55,43.89 v1(23.55,43.59) ; C198.2 v1(75.28,70.1) ; v1(53.56,27.83) 53.61,27.88 C143.2 ; C96.2 v1(28.56,52.98) ; U9.1 12.94,35.07 12.73,34.87 v1(12.73,34.59) ; v1(45.15,6.31) C81.2 v1(45.79,5.7) ; C127.2 v1(87.63,75.11) ; v1(67.03,9.08) 67.03,9.7 C93.2 ; C1.2 v1(8.94,64.31) ; C1.2 v1(10.2,64.31) ; C1.2 9.61,64.53 v1(9.26,64.89) ; R29.1 25.46,41.47 v1(25.25,41.68) ; C148.1 v1(34.67,27.99) ; v1(92.48,45.53) R17.1 v1(93.75,45.53) ; C202.2 v1(73.82,72.79) ; R232.1 12.08,70.13 v1(11.79,70.42) ; R266.1 v1(87.12,67.52) ; C89.2 63.11,11.02 v1(63.02,11.11) ; C205.2 v1(28.96,46.27) ; C201.2 v1(74.22,69.26) ; v1(13.79,36.91) 13.45,36.57 U9.4 12.64,36.57 v1(12.48,36.73) ; v1(98.99,42.01) 98.99,42.31 C10.2 98.26,42.32 v1(98.26,42.03) ; v1(33.42,44.8) C23.2 v1(32.8,45.37) ; C119.2 v1(32.24,21.86) ; v1(78.27,70.49) U24.11 v1(80.98,70.49) ; C6.2 v1(11.75,48.35) ; v1(96.76,38.45) 97.03,38.72 R91.2 v1(97.03,39.86) ; v1(67.41,7.33) 67.39,7.35 C88.2 ; U2.6 96.87,43.18 v1(96.96,43.09) 97.35,42.7 C11.2 ; R262.1 v1(74.22,68.3) ; C126.2 v1(98.61,71.44) ; C36.2 v1(11.34,34.41) ; v1(30.56,14.23) 30.56,14.55 R197.2 ; v1(24.91,43.68) C21.2 25.05,44.39 v1(25.7,44.39) U4.2 26.81,44.39 v1(27.1,44.11) ; v1(31.49,52.55) 31.49,52.11 C18.2 30.77,52.13 v1(30.77,52.83) ; v1(92.03,75.1) C204.2 92.61,75.1 R267.1 ; Q2.2 v1(9.96,69.63) ; C156.1 v1(28.51,21.46) ; C154.1 v1(28.5,15.1) ; v1(78.55,31.38) 78.7,31.24 U5.2 79.7,31.24 v1(79.97,31.51) ; v1(69.55,7.81) 69.19,7.45 C90.2 ; C203.2 v1(87.05,68.93) ; C91.2 v1(66.13,11.06) ; R269.1 v1(96.02,66.03) ; R36.1 v1(80.2,34.15) ; v1(25.31,50.98) U3.2 26.41,50.98 v1(26.57,50.82) ; v1(32.74,51.89) C19.2 v1(32.21,52.46) ; v1(62.03,7.83) 62.73,7.14 C92.2 ; v1(10.63,45.48) 10.81,45.3 C8.2 v1(12.12,45.3) 12.06,45.36 12.06,46.03 C7.2 ; v1(32.05,45.91) 32.05,45.4 C22.2 31.23,45.57 v1(31.23,45.91) ; C12.2 v1(87.24,42.59) ; C122.2 v1(95.46,68.8) ; C155.1 v1(28.54,18.92) ; C14.2 v1(87.24,41.45) ; C121.2 v1(95.46,69.69) ; C45.2 v1(11.98,37.82) ; R259.1 v1(73.28,70.1) ; R233.2 19.69,71.29
  BOTTOM w0.246: C7.2 v1(10.95,46.34) ; C6.2 v1(10.94,47.61)
  BOTTOM w0.254: R5.2 v1(10.29,41.07) ; R7.1 v1(12.84,39.14) ; R53.2 v1(18.92,36.07) ; C194.2 v1(89.25,72.66) ; R6.1 v1(15.01,39.14)
  BOTTOM w0.305: v1(96.13,72.62) U15.2 v1(96.13,70.35) ; D8.1 45.69,15.7 v1(45.18,16.22) ; C83.2 45.18,13.47 v1(45.18,13.7) 45.52,14.04 C84.2 ; v1(49.6,12.99) R68.2 v1(48.98,12.28)
  BOTTOM w0.33: 77.32,15.75 U12.2 75.05,15.75 v1(74.73,15.43)
  BOTTOM w0.508: J13.14 14.06,7.5 ; J13.9 8.35,28.3 ; J13.12 12.62,24.27 12.62,28.42 ; J13.10 8.35,8.39
  vias: v1(0.81,85.98) v1(0.81,80.9) v1(0.81,75.82) v1(0.81,70.74) v1(0.81,65.66) v1(0.81,60.58) v1(0.81,55.5) v1(0.81,50.42) v1(0.81,45.34) v1(0.81,40.26) v1(0.81,35.18) v1(0.81,30.1) v1(0.86,8.07) v1(1.52,34.54) v1(1.67,48.62) v1(1.68,44.92) v1(1.76,35.55) v1(1.71,33.59) v1(2.86,35.72) v1(2.89,48.7) v1(2.97,33.36) v1(3.1,44.7) v1(3.33,41.49) v1(3.59,47.51) v1(3.6,46.38) v1(3.63,45.28) v1(4.14,35.38) v1(4.16,33.97) v1(4.34,63.62) v1(4.46,28.4) v1(5.13,64.42) v1(5.23,37.69) v1(5.66,54.18) v1(5.86,45.33) v1(5.89,85.98) v1(5.89,80.9) v1(5.89,75.82) v1(5.89,70.74) v1(5.93,63.62) v1(5.94,8.07) v1(6.05,50.96) v1(6.15,91.03) v1(6.1,67.69) v1(6.07,46.37) v1(6.21,66.29) v1(6.27,0.73) v1(6.46,44.83) v1(6.75,51.72) v1(6.99,47.68) v1(7.02,36.38) v1(7.26,68.47) v1(7.23,32.2) v1(7.42,56.94) v1(7.58,65.96) v1(7.73,85.4) v1(8,52.45) v1(8.47,86.13) v1(8.48,84.84) v1(8.47,4.13) v1(8.72,45.63) v1(8.7,37.73) v1(8.79,80.6) v1(8.89,82.28) v1(9.01,52.16) v1(9.15,41.57) v1(9.24,35.05) v1(9.3,47.64) v1(9.33,46.42) v1(9.54,90.04) v1(9.54,28.4) v1(10.31,91.15) v1(10.46,85.44) v1(10.5,81.09) v1(10.56,54.02) v1(10.76,65.82) v1(10.81,38.71) v1(11.02,8.07) v1(11.32,32.34) v1(11.35,0.73) v1(11.61,41.74) v1(11.92,60.59) v1(12.19,82.66) v1(12.37,86.16) v1(12.38,84.88) v1(12.44,76.51) v1(12.72,69.33) v1(12.68,62.5) v1(12.87,89.89) v1(12.89,77.99) v1(13.06,85.45) v1(13.09,73.49) v1(13.1,41.55) v1(13.53,52.47) v1(13.55,4.13) v1(13.75,63.84) v1(14.05,42.53) v1(14.18,43.56) v1(14.51,66.2) v1(14.5,50.05) v1(14.58,47.89) v1(14.62,43.09) v1(14.62,28.4) v1(14.75,87.22) v1(14.69,83.07) v1(15.05,42.6) v1(15.13,63.65) v1(15.19,43.66) v1(15.3,39.85) v1(15.66,72.33) v1(15.9,66.24) v1(15.94,44.68) v1(16.04,41.82) v1(16.08,69.7) v1(16.34,61.23) v1(16.35,37.27) v1(16.43,0.73) v1(16.51,33.91) v1(16.55,32.38) v1(16.75,7.94) v1(16.97,91.19) v1(17.11,41.43) v1(17.17,66.32) v1(17.36,78.74) v1(17.36,73.66) v1(17.48,63.09) v1(17.65,3.21) v1(17.65,1.79) v1(17.71,46.43) v1(17.89,84.53) v1(17.95,65.73) v1(18.16,87.2) v1(18.1,10.53) v1(18.3,88.69) v1(18.36,37.79) v1(18.5,46.42) v1(18.68,66.29) v1(18.76,27.19) v1(18.92,87.32) v1(18.97,41.57) v1(19.04,1.23) v1(19.34,84.28) v1(19.44,60.62) v1(19.46,44.65) v1(19.65,25.48) v1(19.77,85.99) v1(19.83,47.73) v1(20,42.61) v1(20,35.76) v1(20.36,49.55) v1(20.44,53.94) v1(20.54,88.52) v1(20.6,46.41) v1(20.86,37.85) v1(21.08,1.23) v1(21.2,42.4) v1(21.5,85.93) v1(21.48,81.55) v1(21.51,0.73) v1(21.74,66.25) v1(21.8,84.25) v1(21.85,41.3) v1(21.94,43.56) v1(21.95,30.25) v1(22.05,35.34) v1(22.06,1.93) v1(22.11,87.29) v1(22.12,44.72) v1(22.16,3.5) v1(22.2,88.54) v1(22.57,91.02) v1(22.85,79.86) v1(22.77,5.77) v1(22.88,81.47) v1(22.93,25.74) v1(23.06,40.2) v1(23.37,4.42) v1(23.5,42.38) v1(23.67,50.16) v1(23.8,72.62) v1(23.84,70.32) v1(23.83,65.95) v1(23.89,39.61) v1(24.02,48.81) v1(24.36,83.38) v1(24.75,50.22) v1(24.77,4.38) v1(24.94,48.18) v1(25.04,77.69) v1(25.16,40.9) v1(25.18,5.71) v1(25.44,72.39) v1(25.56,36.19) v1(25.54,32.05) v1(25.66,39.4) v1(25.62,28.37) v1(25.69,66.03) v1(25.74,53.66) v1(25.84,56.32) v1(25.84,11.29) v1(26.16,69.89) v1(26.09,24.54) v1(26.61,49.77) v1(26.59,0.73) v1(26.88,84.03) v1(26.88,78.95) v1(26.88,58.33) v1(27.43,88.26) v1(27.55,74.94) v1(27.52,65.93) v1(27.67,81.87) v1(27.96,3.21) v1(28.06,72.69) v1(28.01,55.72) v1(28.11,38.74) v1(28.35,91.06) v1(28.31,82.45) v1(28.36,74.41) v1(28.56,8.15) v1(28.67,48.44) v1(28.67,22.78) v1(28.82,71.17) v1(28.91,25.68) v1(28.97,41.71) v1(29.16,66.17) v1(29.1,15.78) v1(29.29,20.75) v1(29.52,74.64) v1(29.64,87.46) v1(29.65,33.4) v1(29.92,72.62) v1(29.88,24.5) v1(29.92,12.37) v1(30.16,18.82) v1(30.31,21.95) v1(30.27,4.61) v1(30.41,58.68) v1(30.44,51.06) v1(30.72,39.57) v1(30.81,28.76) v1(31,17.04) v1(31.37,20.71) v1(31.42,18.8) v1(31.71,74.44) v1(31.67,0.73) v1(31.96,84.03) v1(32.13,35.86) v1(32.24,67.52) v1(32.23,53.8) v1(32.46,59.27) v1(32.85,36.56) v1(32.88,33.81) v1(33.06,34.59) v1(32.99,7.17) v1(33.24,33) v1(33.5,25.68) v1(33.65,76.24) v1(33.6,12.04) v1(33.76,19.8) v1(33.76,18.8) v1(33.95,68.98) v1(33.97,59.3) v1(34,36.21) v1(34.23,50.55) v1(34.31,23.05) v1(34.4,32.01) v1(34.4,6) v1(34.52,79.19) v1(34.56,17.97) v1(34.58,55.18) v1(34.76,19.8) v1(34.76,18.8) v1(34.96,56.76) v1(35.24,70.23) v1(35.35,51.65) v1(35.54,34.7) v1(35.6,57.62) v1(35.58,22.31) v1(35.71,91.15) v1(35.71,86.07) v1(35.76,80.87) v1(35.76,19.8) v1(35.76,18.8) v1(35.76,17.8) v1(35.67,10.17) v1(35.86,66.25) v1(35.79,32.92) v1(36.35,78.87) v1(36.55,28.71) v1(36.75,0.73) v1(36.86,36.03) v1(36.77,33.76) v1(37.01,12) v1(37.14,21.28) v1(37.21,52) v1(37.24,15.44) v1(37.28,34.38) v1(37.44,50.43) v1(37.66,54.06) v1(37.86,71.26) v1(37.94,68.95) v1(37.87,9.84) v1(38.13,16.6) v1(38.23,80.65) v1(38.24,38.41) v1(38.24,27.56) v1(38.2,13.07) v1(38.33,17.7) v1(38.54,73.7) v1(38.62,36.91) v1(38.62,34.17) v1(38.59,32.76) v1(38.71,46.23) v1(38.86,58.08) v1(39.16,29.95) v1(39.31,59.73) v1(39.36,55.14) v1(39.43,4.2) v1(39.56,26.34) v1(39.95,54.44) v1(40.79,91.15) v1(40.79,86.07) v1(40.79,52.88) v1(40.92,2.81) v1(41.04,46.01) v1(40.97,44.93) v1(41.07,50.24) v1(41.1,32.92) v1(41.19,27.73) v1(41.25,12.97) v1(41.3,30.35) v1(41.28,24.54) v1(41.28,19.29) v1(41.62,38.4) v1(41.62,36.9) v1(41.62,34.71) v1(41.7,83.14) v1(41.8,53.97) v1(41.8,6.09) v1(41.83,0.73) v1(42.01,47.54) v1(42.07,21.13) v1(42.23,31.24) v1(42.28,33.66) v1(42.34,16.29) v1(42.29,10.77) v1(42.64,61.01) v1(42.9,73.83) v1(42.87,63.44) v1(42.99,36.9) v1(43.06,13.54) v1(43.1,66.37) v1(43.23,77.44) v1(43.21,34.46) v1(43.52,32.45) v1(43.57,30.41) v1(43.54,16.26) v1(43.63,47.58) v1(43.68,49.98) v1(43.84,56.81) v1(43.97,12.49) v1(44.13,51.45) v1(44.71,53.38) v1(44.84,36.89) v1(44.84,24.29) v1(44.78,20.16) v1(44.91,73.74) v1(44.98,64.49) v1(45.24,60.41) v1(45.25,22.29) v1(45.38,62.76) v1(45.37,34.45) v1(45.54,36.91) v1(45.73,25.89) v1(45.8,33.72) v1(45.82,18.6) v1(45.87,91.15) v1(45.87,86.07) v1(45.88,19.66) v1(45.87,10.11) v1(46.01,11.17) v1(46.26,36.91) v1(46.23,34.44) v1(46.33,41.61) v1(46.3,33.18) v1(46.49,20.98) v1(46.68,40.64) v1(46.9,57.01) v1(46.87,56.13) v1(46.91,0.73) v1(47.02,22.18) v1(47.21,83.1) v1(47.18,50.07) v1(47.17,42.54) v1(47.26,40.67) v1(47.18,16.86) v1(47.31,53.66) v1(47.38,18.23) v1(47.44,8.63) v1(47.64,25.13) v1(47.68,28.03) v1(47.92,73.41) v1(47.9,3.09) v1(47.97,43.49) v1(48.31,77.44) v1(48.31,42.88) v1(48.41,41.15) v1(48.45,10.23) v1(48.5,60.61) v1(48.68,30.17) v1(48.92,74.09) v1(48.96,33.1) v1(48.93,30.87) v1(48.87,26.19) v1(49.09,23.14) v1(49.35,28.72) v1(49.38,59.35) v1(49.49,53.64) v1(49.57,49.99) v1(49.6,16.88) v1(50.14,16.29) v1(50.57,27.78) v1(50.6,19.64) v1(50.76,59.31) v1(50.69,8.83) v1(50.95,91.15) v1(50.95,86.07) v1(51.17,41.89) v1(51.37,69.03) v1(51.75,36.77) v1(51.94,50.05) v1(51.96,27.53) v1(51.97,53.22) v1(52.01,15.86) v1(51.99,0.73) v1(52.19,76.3) v1(52.32,42.87) v1(52.32,42.23) v1(52.31,41.6) v1(52.52,83.1) v1(52.84,73.42) v1(52.82,26.75) v1(52.9,23.14) v1(53.04,68.48) v1(52.98,19.8) v1(53.07,67.31) v1(53.31,71.41) v1(53.39,77.44) v1(53.41,59.35) v1(53.54,70.48) v1(53.63,66.53) v1(54.02,13.27) v1(54.26,49.84) v1(54.44,5.11) v1(54.58,53.43) v1(54.85,68.78) v1(54.79,41.25) v1(54.79,40.71) v1(54.79,40.15) v1(54.88,10.66) v1(55,30.28) v1(55.07,17.6) v1(55.18,2.56) v1(55.49,25.26) v1(55.64,18.13) v1(55.77,8.83) v1(56.03,91.15) v1(56.03,86.07) v1(56,21.82) v1(56.23,25.05) v1(56.24,19.63) v1(56.74,56.08) v1(56.96,75.08) v1(56.88,67.6) v1(56.95,59.2) v1(57.11,21.83) v1(57.07,0.73) v1(57.25,68.86) v1(57.24,12.79) v1(57.24,3.79) v1(57.57,83.14) v1(57.58,26.43) v1(57.71,42.44) v1(57.71,41.81) v1(57.77,49.08) v1(57.92,57.98) v1(57.91,14.79) v1(58.07,6.75) v1(58.31,73.39) v1(58.47,77.44) v1(58.55,69.8) v1(58.49,17.76) v1(58.75,48.97) v1(58.74,19.06) v1(58.68,15.14) v1(58.93,43.69) v1(58.96,41.23) v1(58.96,21.85) v1(58.98,7.89) v1(59.1,65.8) v1(59.14,46.07) v1(59.1,19.84) v1(59.26,41.92) v1(59.47,60.23) v1(59.72,66.49) v1(59.72,51.03) v1(59.84,3.24) v1(59.98,49) v1(59.99,22.23) v1(60.09,59.42) v1(60.23,69.49) v1(60.2,38.72) v1(60.37,16.48) v1(60.54,50.73) v1(60.53,14.9) v1(60.81,10.82) v1(60.92,67.22) v1(61.11,91.15) v1(61.11,86.07) v1(61.21,39.01) v1(61.45,33.07) v1(61.53,46.13) v1(61.64,41.62) v1(61.62,36.39) v1(61.77,41) v1(61.94,64.24) v1(61.91,50.74) v1(61.92,11.07) v1(62,53.3) v1(62.15,39.01) v1(62.16,4.33) v1(62.15,0.73) v1(62.2,83.3) v1(62.43,62.43) v1(62.5,36.78) v1(62.64,52.78) v1(62.62,33.07) v1(62.68,48.78) v1(62.86,44.91) v1(62.96,58.38) v1(62.94,13.84) v1(63.04,59.7) v1(62.98,31.74) v1(63.12,55.89) v1(63.22,36.37) v1(63.28,64.93) v1(63.44,19.49) v1(63.46,18.3) v1(63.57,52.58) v1(63.7,44.21) v1(63.71,42.93) v1(63.7,36.81) v1(63.7,13.29) v1(63.84,77.46) v1(63.79,66.51) v1(64.13,33.08) v1(64.36,83.31) v1(64.31,45.14) v1(64.31,31.59) v1(64.43,55.71) v1(64.37,51.24) v1(64.56,61.15) v1(64.65,59.01) v1(64.57,18.34) v1(64.65,9.06) v1(64.68,11.14) v1(64.93,13.33) v1(64.89,2.18) v1(65.06,21.87) v1(65.39,63.21) v1(65.41,33.08) v1(65.53,12.73) v1(65.61,18.36) v1(65.72,31.46) v1(65.77,39.31) v1(65.91,24.55) v1(65.99,84.93) v1(66.05,56.25) v1(66.1,12.26) v1(66.19,91.15) v1(66.25,87.17) v1(66.17,59.98) v1(66.35,33.98) v1(66.29,6.66) v1(66.38,20.34) v1(66.56,40.13) v1(66.51,28.12) v1(66.64,74.22) v1(66.61,70.87) v1(66.62,61.87) v1(66.75,11.3) v1(66.69,5.57) v1(66.91,53.28) v1(66.96,26.1) v1(66.9,24.55) v1(67.06,83.67) v1(66.98,23.03) v1(67.12,49.52) v1(67.17,51.84) v1(67.23,0.73) v1(67.27,28.13) v1(67.42,12.1) v1(67.46,5.57) v1(67.76,35.46) v1(67.86,77.54) v1(67.85,28.12) v1(67.93,62.54) v1(68.06,38.29) v1(68.1,41.63) v1(68.14,24.55) v1(68.08,12.74) v1(68.19,59.45) v1(68.29,21.89) v1(68.34,18.66) v1(68.41,32.67) v1(68.47,49.15) v1(68.48,28.14) v1(68.65,44.85) v1(68.69,13.34) v1(68.83,3.52) v1(68.88,16.11) v1(69.02,85.4) v1(69.13,36.5) v1(69.17,88.09) v1(69.2,71.76) v1(69.31,39.44) v1(69.43,42.96) v1(69.53,44.98) v1(69.62,38.37) v1(69.66,28.15) v1(69.59,13.51) v1(69.84,61.18) v1(69.83,19.51) v1(69.83,6.18) v1(69.87,49.16) v1(70.24,55.75) v1(70.34,53.23) v1(70.42,32.54) v1(70.51,59.41) v1(70.62,29.21) v1(70.61,8.23) v1(70.61,3.15) v1(70.71,34.34) v1(70.7,23.03) v1(70.79,24.55) v1(70.77,15.9) v1(71.27,91.15) v1(71.37,40.21) v1(71.37,36.58) v1(71.49,28.13) v1(71.62,75.66) v1(71.62,70.58) v1(71.69,41.99) v1(71.68,30.65) v1(71.81,80.77) v1(71.78,29.78) v1(72.04,88.33) v1(72.32,6.05) v1(72.31,0.73) v1(72.42,29.98) v1(72.49,42.98) v1(72.55,17.54) v1(72.85,36.32) v1(72.94,41.81) v1(72.9,12.28) v1(72.97,29.78) v1(73.16,22.02) v1(73.26,38.51) v1(73.21,19.66) v1(73.38,8.8) v1(73.49,34.61) v1(73.51,28.13) v1(73.57,29.08) v1(73.65,25.97) v1(73.76,56.64) v1(73.87,88.42) v1(73.87,42.98) v1(74.11,66.77) v1(74.1,5.97) v1(74.25,52.46) v1(74.33,40.19) v1(74.52,82.37) v1(74.58,59.9) v1(74.73,25.91) v1(74.86,42.04) v1(74.84,20.54) v1(74.89,78.92) v1(74.89,38.52) v1(74.96,10.32) v1(74.99,24.59) v1(75.1,73.96) v1(75.25,89.44) v1(75.17,59.27) v1(75.18,13.69) v1(75.34,28.13) v1(75.45,56.37) v1(75.46,49.6) v1(75.46,44.8) v1(75.55,25.91) v1(75.48,12.39) v1(75.8,77.57) v1(75.92,41.13) v1(76.01,70.33) v1(76.18,78.96) v1(76.35,91.15) v1(76.3,59.19) v1(76.37,76) v1(76.43,45.25) v1(76.37,42.9) v1(76.56,24.56) v1(76.61,35.52) v1(76.58,20.97) v1(76.76,25.91) v1(76.77,33.72) v1(76.93,55.27) v1(77.41,77.95) v1(77.43,28.15) v1(77.41,2.77) v1(77.39,0.73) v1(77.63,67.43) v1(77.6,57.43) v1(77.8,10.97) v1(77.88,76.26) v1(77.96,52.16) v1(77.93,20.87) v1(77.97,83.76) v1(78.04,78.94) v1(78.07,25.96) v1(78.98,65.41) v1(79.25,49.77) v1(79.59,75.37) v1(79.66,35.5) v1(79.63,15.16) v1(79.75,78.78) v1(79.76,19.42) v1(79.75,11.22) v1(80.18,73.16) v1(80.7,32.07) v1(80.68,27.06) v1(80.99,53.58) v1(81.05,51.7) v1(81.01,48.46) v1(81.09,35.28) v1(81.33,89.52) v1(81.31,87.42) v1(81.32,81.46) v1(81.43,91.15) v1(81.46,26.04) v1(81.53,67.37) v1(81.49,15.15) v1(81.58,60.23) v1(81.63,46.48) v1(81.72,32.17) v1(81.67,24.73) v1(81.8,17.26) v1(82.01,78.22) v1(81.99,12.18) v1(82.08,63.22) v1(82.23,70.72) v1(82.33,73.06) v1(82.42,31.53) v1(82.53,81.44) v1(82.53,4.83) v1(82.47,0.73) v1(82.65,8.87) v1(83.05,83.76) v1(83.15,58.95) v1(83.36,75.19) v1(83.44,72.13) v1(83.39,69.23) v1(84.06,65.41) v1(84.61,22.14) v1(84.75,24.82) v1(84.72,14.52) v1(84.81,67.83) v1(84.81,19.05) v1(84.78,16.93) v1(84.78,10.39) v1(85.26,3.29) v1(85.33,75.62) v1(85.41,80.46) v1(85.42,73.38) v1(85.44,54.9) v1(85.46,46.85) v1(85.5,57.31) v1(85.54,48.88) v1(85.74,60.18) v1(85.83,66.57) v1(85.81,8.78) v1(85.93,6.1) v1(86.03,51.61) v1(86.34,61.06) v1(86.43,58.98) v1(86.51,91.15) v1(86.58,87.63) v1(86.73,52.62) v1(86.89,32.75) v1(86.99,64.15) v1(87.17,35.57) v1(87.46,37.91) v1(87.55,2.31) v1(87.55,0.73) v1(87.7,70.32) v1(87.74,40.15) v1(87.67,25.97) v1(87.7,11.21) v1(87.68,7.86) v1(87.9,48.5) v1(87.9,27.53) v1(87.91,22.49) v1(88.13,83.76) v1(88.19,19.89) v1(88.21,14.19) v1(88.17,4.1) v1(88.27,18.68) v1(88.3,17.53) v1(88.28,16.46) v1(88.28,15.13) v1(88.33,12.78) v1(88.41,65.77) v1(88.37,40.66) v1(88.55,61.22) v1(88.52,34.33) v1(88.51,20.98) v1(88.59,80.41) v1(88.69,59.01) v1(88.96,27.94) v1(89.04,78.03) v1(88.99,29.06) v1(89.03,23.86) v1(89.19,31.58) v1(89.33,88.36) v1(89.39,76.27) v1(89.43,6.2) v1(89.51,70.6) v1(89.61,68.54) v1(89.88,56.53) v1(89.87,52.76) v1(89.94,21.04) v1(90.07,35.69) v1(90.24,63.44) v1(90.18,24.71) v1(90.31,7.87) v1(90.76,75.25) v1(90.78,72.95) v1(90.92,77.79) v1(90.89,11.04) v1(91.03,35.66) v1(91.13,61.28) v1(91.15,33.11) v1(91.29,2.43) v1(91.38,66.9) v1(91.59,91.15) v1(91.58,71.79) v1(91.78,69.21) v1(91.8,35.62) v1(91.97,40.24) v1(92.07,42.9) v1(92.16,7.49) v1(92.08,3.29) v1(92.22,63.52) v1(92.32,55.66) v1(92.35,54.57) v1(92.3,53.34) v1(92.34,51.94) v1(92.32,50.11) v1(92.3,32.54) v1(92.31,29.7) v1(92.27,27.97) v1(92.43,57.22) v1(92.49,47.8) v1(92.62,48.8) v1(92.63,0.73) v1(92.68,80.27) v1(92.73,39.66) v1(92.82,70.79) v1(92.78,35.62) v1(92.88,77.96) v1(92.88,16.53) v1(92.91,15.24) v1(93,58.55) v1(93.03,21.66) v1(92.98,19.81) v1(93.01,18.62) v1(92.97,17.51) v1(93.12,27.97) v1(93.07,14.31) v1(93.07,13.17) v1(93.21,83.76) v1(93.23,30.98) v1(93.19,7.47) v1(93.36,51.81) v1(93.27,11.47) v1(93.39,60.38) v1(93.39,43.87) v1(93.5,50.08) v1(93.65,63.75) v1(93.61,40.06) v1(93.86,8.11) v1(93.96,40.6) v1(94.16,65.32) v1(94.18,27.61) v1(94.26,18.81) v1(94.27,72.28) v1(94.41,88.36) v1(94.57,73.51) v1(94.7,69.42) v1(94.69,62.49) v1(94.73,33.63) v1(94.71,26.74) v1(94.72,22.35) v1(94.9,41.17) v1(94.95,20.13) v1(94.95,19.12) v1(94.95,18.13) v1(94.91,11.59) v1(94.94,10.37) v1(95.21,45.44) v1(95.26,43.83) v1(95.43,77.27) v1(95.56,76.27) v1(95.65,29.29) v1(96.01,82.02) v1(96.03,3.73) v1(96.26,42.1) v1(96.18,9.79) v1(96.36,6.65) v1(96.43,58.43) v1(96.55,55.85) v1(96.61,53.12) v1(96.67,91.15) v1(96.9,47.51) v1(97.03,65) v1(97.23,38.12) v1(97.21,37.07) v1(97.23,35.91) v1(97.46,58.55) v1(97.47,52.34) v1(97.49,27.28) v1(97.52,24.39) v1(97.55,23.4) v1(97.53,12.03) v1(97.48,8.98) v1(97.59,10.65) v1(97.76,30.8) v1(97.75,28.44) v1(97.69,17.9) v1(97.71,0.73) v1(97.83,26.01) v1(97.77,15.34) v1(98.01,50.88) v1(98.01,45.89) v1(98.04,23.88) v1(98.33,60.84) v1(98.33,59.11) v1(98.52,24.33) v1(98.53,23.38) v1(98.7,79.45) v1(98.7,76.34) v1(98.74,65.4) v1(98.77,35.74) v1(98.97,55.67) v1(99.09,85.32) v1(99.19,68.99) v1(99.28,49.96) v1(99.32,31.7) v1(99.27,28.87) v1(99.3,14.41) v1(99.37,58.35) v1(99.46,57.01) v1(99.38,33.77) v1(99.45,25.25) v1(99.38,22.58) v1(99.57,54.42) v1(99.65,7.6) v1(99.76,64.2) v1(99.72,51.87) v1(99.72,45.23) v1(99.94,35.48) v1(100.08,25.95) v1(100.35,23.99) v1(100.52,26.65) v1(100.69,19.49) v1(100.79,11.4) v1(100.94,8.9) v1(101.03,29.97) v1(101.31,35.94) v1(101.56,38.76) v1(102.02,85.9) v1(102.05,81.95) v1(102.05,76.87) v1(102.05,71.79) v1(102.05,66.71) v1(102.05,61.63) v1(102.05,56.55) v1(102.05,51.47) v1(102.05,46.39) v1(102.05,41.31) v1(102.05,36.23) v1(102.05,31.15) v1(102.05,26.07) v1(102.05,20.99) v1(102.05,15.91) v1(102.05,10.83) v1(102.05,5.75)
VBAT2: length 89.5
  TOP w0.254: v1(76.53,45.78) 80.76,50 89.42,50 R2.2 ; v1(41.09,44.36) 41.09,44.37 27.68,44.37 27.12,44.92 25.46,44.92 24.7,44.16 v1(12.4,44.16)
  BOTTOM w0.254: v1(41.09,44.36) 44.68,47.96 63.2,47.96 64.28,46.87 75.44,46.87 v1(76.53,45.78) ; 4.23,37 9.38,37 R50.2 R49.2
VCC_3V3: length 75.2
  TOP w0.254: R234.1 87.13,9.55 v1(87.09,9.59)
  TOP w0.381: v1(82.25,35.55) 82.25,37.93 80.41,39.76 C181.1 76.15,38.85 U21.8
  TOP w0.457: v1(78.69,15.81) 78.69,16.24 R97.1
  L3_PWR w0.381: v1(87.94,34.9) 82.9,34.9 v1(82.25,35.55)
  BOTTOM w0.203: R96.2 92.07,39.17 91.66,38.76
  BOTTOM w0.508: U12.1 77.8,16.7 C86.1 v1(78.69,15.81) 78.69,14.77 R141.1 78.66,13.68 82.75,9.59 v1(87.09,9.59) 90.26,9.59 91.66,10.99 91.66,30.1 87.94,33.82 v1(87.94,34.9) 87.94,36.47 89.11,37.64
VCC_5V: length 140
  TOP w0.254: R10.2 80.71,54.15 70.14,43.58 v1(70.06,43.58)
  TOP w0.305: R24.2 v1(42.83,38.68)
  TOP w0.508: v1(14.17,45.59) 13.78,45.98 11.98,45.98 10.96,44.96 10.96,40.85 v1(10.29,40.18) 13.54,40.18 16.57,43.21 v1(19.61,43.21) ; v1(26.36,40.06) 29.94,40.06 30.56,40.68 33.45,40.68 35.15,38.98 42.53,38.98 v1(42.83,38.68)
  L3_PWR w0.508: v1(70.06,43.58) 80.41,43.58 89.18,34.82 v1(89.18,33.68)
  BOTTOM w0.254: 97.29,25.75 U23.13 ; R4.2 v1(10.29,40.18) ; R9.2 v1(19.61,43.21)
  BOTTOM w0.432: 97.29,25.75 97.29,26.27 C184.2
  BOTTOM w0.508: v1(89.18,33.68) 96.2,26.66 C184.2 ; v1(19.61,43.21) 21.31,43.21 24.46,40.06 v1(26.36,40.06) ; v1(70.06,43.58) 63.14,43.58 61.21,45.51 58.17,45.51 57.71,45.96 46.39,45.96 42.21,41.78 42.21,40.59 42.83,39.96 v1(42.83,38.68)
  vias: v1(8.72,49.45) v1(9.41,49.04) v1(10.27,49.03) v1(11.03,49.02)
VCC_IN: length 2.5
  BOTTOM w0.254: v1(11.94,43.33) v1(12.48,43.33) U1.15 ; v1(12.95,45.09) v1(13.49,45.09) 13.87,44.71 U1.1
  vias: v1(17.78,50.86) v1(17.8,49.84) v1(18.96,50.82) v1(19,49.86)
VCC_SOC: length 22.3
  TOP w0.254: v1(60.73,70.73) 60.13,70.73 R127.2 60.35,71.5 v1(60.65,71.5)
  TOP w0.508: v1(23.03,64.01) 14.15,72.9 R56.2
  vias: v1(41.94,62.72) v1(42.68,62.43)
VCCQ_3V3: length 28.6
  TOP w0.203: U11.P5 U11.N4 U11.P3
  TOP w0.254: v1(63.89,9.07) 63.88,9.07 U11.M4 U11.N4 ; v1(62.03,9.66) 62.12,9.57 U11.P3 ; v1(67.54,7.88) 67.73,8.07 U11.C6 ; U11.P5 62.23,8.57 ; v1(72.46,9.27) 72.38,9.35 72.38,14.19 R77.1 R76.1 R75.1 69.53,15.23 R74.1
  BOTTOM w0.254: v1(62.03,9.66) 62.6,9.66 R78.1 v1(63.89,9.07) 63.7,9.25 C89.1 ; v1(62.03,8.44) 61.99,8.41 R79.2 ; R73.1 v1(72.46,9.27) ; R73.1 R72.1 ; R73.1 72.45,9.89 R70.1 R71.1 70.44,9.89 C90.1
  BOTTOM w0.381: v1(68.01,3.21) C90.1 67.58,7.88 v1(67.54,7.88)
  vias: v1(59.98,7.46) v1(60.31,7.86)
VDD_TFT: length 5.4
  TOP w0.305: J15.6 94.91,26.13
  TOP w0.381: R151.2 91.24,26.33 C104.1 C103.1 93.19,26.13 94.91,26.13
VDDIO2: length 4.7
  TOP w0.254: U7.C4 v1(59.55,38.07)
  BOTTOM w0.381: v1(59.55,38.07) 60.82,38.07 C172.1 61.94,38.28 C173.1 62.79,38.27 R138.2 62.8,39.21 R185.2
VDDMSC0: length 8
  TOP w0.305: J6.4 v1(47.38,16.16)
  BOTTOM w0.254: 46.76,14.63 R62.1 R63.1 ; 47.68,14.65 R61.1 R65.1 R64.1
ADC_AVDD: length 3.5
  TOP w0.254: U7.N16 v1(52.4,29.63) 52.73,29.3 U7.N17
  BOTTOM w0.381: v1(52.4,29.63) 52.07,29.63 C74.1 C73.1 50.87,29.34 FB7.2
ALS_MEASURE_EN_PB22: length 114.5
  TOP w0.102: R114.2 R112.1 61.71,80.02 61.71,70.23 v1(60.31,68.83) ; v1(62.86,21.99) 62.86,24.68 58.92,28.62 58.92,30.26 U7.D15
  BOTTOM w0.102: v1(62.86,21.99) 62.86,22.26 62.45,22.66 61.16,22.66 59.77,21.27 49.79,21.27 39.86,31.2 39.86,46.77 38.82,47.8 38.82,55.21 41.95,58.33 46.74,58.33 53.7,65.29 56.77,65.29 v1(60.31,68.83)
BAT_ADC_IOT: length 6.2
  TOP w0.102: R2.1 89.9,49.44 R3.2 90.79,49.44 C5.1 91.74,49.37 95.11,49.37 J14.14
BAT_ALRT_N_IOT: length 90.3
  TOP w0.102: v1(69.68,45.53) 70.35,45.53 83.11,58.29 92.06,58.29 93.96,56.39 J14.3 ; v1(17.3,37.6) 22.55,42.86 31.51,42.86 32.37,43.72 40.61,43.72 40.89,43.44 41.31,43.44 v1(41.77,43.9)
  BOTTOM w0.102: U9.5 16.9,36.57 R47.2 v1(17.3,37.6) ; v1(69.68,45.53) 68.08,45.53 67.43,46.19 63.91,46.19 62.72,47.38 45.25,47.38 v1(41.77,43.9)
BOOTSEL0: length 47.5
  TOP w0.102: v1(72.04,42.58) 71.76,42.58 64.15,34.97 61,34.97 U7.A9 ; v1(75.21,42.67) 75.87,43.33 80.27,43.33 81.76,44.82 100.18,44.82 R270.1 SW3.2
  BOTTOM w0.102: v1(75.21,42.67) 75.12,42.58 v1(72.04,42.58)
BOOTSEL1: length 8.2
  TOP w0.102: R271.1 66.95,36.5 R272.2 65.59,35.95 64.33,34.69 61.15,34.69 60.65,34.19 60.19,34.19 U7.B9
BT656_D0_PD00: length 4.2
  TOP w0.102: R144.2 v1(88.85,19.85)
  BOTTOM w0.102: J12.5 87.14,21.57 v1(88.85,19.85)
BT656_D1_PD01: length 7.2
  TOP w0.102: R146.2 v1(88.85,18.71)
  BOTTOM w0.102: v1(88.85,18.71) 87.2,20.36 84.67,20.36 J12.6
BT656_D2_PD02: length 4.1
  TOP w0.102: R150.2 v1(88.85,17.56)
  BOTTOM w0.102: J12.7 87.39,19.03 v1(88.85,17.56)
BT656_D3_PD03: length 7.1
  TOP w0.102: R155.2 v1(88.85,16.42)
  BOTTOM w0.102: v1(88.85,16.42) 87.47,17.81 84.69,17.81 J12.8
BT656_D4_PD04: length 4
  TOP w0.102: R158.2 v1(88.85,15.28)
  BOTTOM w0.102: J12.9 87.64,16.49 v1(88.85,15.28)
BT656_D5_PD05: length 7
  TOP w0.102: R161.2 v1(88.85,14.13)
  BOTTOM w0.102: J12.10 84.63,15.32 87.58,15.32 88.77,14.13 v1(88.85,14.13)
BT656_D6_PD06: length 3.9
  TOP w0.102: R163.2 v1(88.85,12.99)
  BOTTOM w0.102: J12.11 87.9,13.95 v1(88.85,12.99)
BT656_D7_PD07: length 6.9
  TOP w0.102: R166.2 v1(88.85,11.85)
  BOTTOM w0.102: v1(88.85,11.85) 88.67,11.85 87.85,12.67 84.74,12.67 J12.12
BT656_PCLK_PD08: length 4.1
  TOP w0.102: R169.2 v1(88.85,22.52)
  BOTTOM w0.102: J12.3 87.26,24.11 v1(88.85,22.52)
BT_UART0_CTS_PC11: length 39
  TOP w0.102: U7.C5 59.56,36.77 60.08,36.77 60.28,36.57 61.13,36.57 61.76,37.2 64.25,37.2 80.05,53 88.78,53 90.09,54.3 R218.1
BT_UART0_RTS_PC12: length 38.7
  TOP w0.102: R223.1 83.09,57.86 63.05,37.81 61.58,37.81 60.87,37.1 U7.A5
BT_UART0_RXD_PC09: length 38.6
  TOP w0.102: R213.1 90.35,52.25 80.18,52.25 63.67,35.74 61.03,35.74 60.66,36.11 59.57,36.11 U7.C6
BT_UART0_TXD_PC08: length 41.1
  TOP w0.102: U7.B6 59.98,36.34 60.75,36.34 61.12,35.98 63.45,35.98 80.09,52.61 v1(86.09,52.61) ; R187.1 v1(86.46,56.08)
  BOTTOM w0.102: v1(86.09,52.61) 86.09,55.71 v1(86.46,56.08)
BT_UART_CTS/PIR_PWR_EN_IOT: length 3.9
  TOP w0.102: R220.2 R218.2 92.12,53.85 J14.7
BT_UART_RTS/LED_R_IOT: length 5.8
  TOP w0.102: R223.2 R225.2 92.89,55.75 95.15,55.75 J14.6
BT_UART_RXD/USART2_TX_IOT: length 5.6
  TOP w0.102: R215.2 R213.2 92.12,52.52 92.79,53.2 95.13,53.2 J14.8
BT_UART_TXD/USB_DET_IOT: length 3.8
  TOP w0.102: R187.2 R188.2 91.74,55.12 J14.5
CHARG_DET_N_IOT: length 91.8
  TOP w0.102: v1(15.37,40.51) 17.08,42.22 20.22,42.22 21.13,43.12 31.36,43.12 32.21,43.97 40.99,43.97 v1(41.15,43.81) ; J14.4 95.16,57.01 93.83,57.01 91.84,59 R8.1 91.19,58.53 82.8,58.53 70.25,45.97 v1(70.12,45.97)
  BOTTOM w0.102: v1(41.15,43.81) 41.15,43.88 44.89,47.62 62.88,47.62 64.04,46.46 67.7,46.46 68.19,45.97 v1(70.12,45.97) ; U1.9 v1(15.37,40.51)
CLK_CTRL: length 4.1
  TOP w0.102: R199.2 34.79,13.68 ; 34.79,13.68 R200.1 ; 34.79,13.68 35.26,14.15 35.26,15.12 34.51,15.87 U19.12
CODEC_AVDD: length 5
  TOP w0.254: U7.R1 v1(51.1,40.03)
  BOTTOM w0.381: FB8.2 50.49,42.93 C61.1 C62.1 50.18,42.04 50.81,41.41 50.81,40.32 v1(51.1,40.03)
CSI_CLKN_DVP_D4: length 15.1
  TOP w0.104: R124.1 50.62,51.22 50.62,49.45 TP26.1 50.62,48.87 50.62,48.41 51.08,47.95 51.08,47.78 51.05,47.76 51.05,47.59 51.18,47.46 51.35,47.46 51.37,47.49 51.55,47.49 51.67,47.37 51.67,47.19 51.64,47.17 51.64,47 51.77,46.87 51.94,46.87 51.96,46.9 52.13,46.9 52.26,46.78 52.26,46.6 52.23,46.58 52.23,46.41 52.36,46.28 52.53,46.28 52.55,46.31 52.72,46.31 53.44,45.59 53.44,39.12 U7.M2
CSI_CLKP_DVP_D5: length 15
  TOP w0.104: U7.L3 54.03,38.55 53.7,38.87 53.7,45.7 50.88,48.52 50.88,48.87 TP25.1 50.88,49.45 50.88,51.22 R109.1
CSI_DATAN0_DVP_D0: length 13.6
  TOP w0.104: R102.1 53.31,51.21 53.31,49.45 TP21.1 53.31,48.86 53.31,48.6 54.33,47.59 54.33,39.57 54.03,39.27 U7.L2
CSI_DATAN1_DVP_D2: length 15.8
  TOP w0.104: U7.N1 52.79,39.76 52.79,43.99 51.86,44.92 51.69,44.92 51.63,44.86 51.46,44.86 51.34,44.98 51.34,45.16 51.39,45.21 51.39,45.38 51.27,45.51 51.1,45.51 51.04,45.45 50.87,45.45 50.75,45.57 50.75,45.75 50.8,45.8 50.8,45.97 50.68,46.09 50.51,46.09 50.45,46.04 50.28,46.04 50.16,46.16 50.16,46.33 50.22,46.39 50.22,46.56 50.09,46.68 49.92,46.68 49.87,46.63 49.69,46.63 49.57,46.75 49.57,46.92 49.63,46.98 49.63,47.15 48.28,48.5 48.28,48.86 TP24.1 48.28,49.45 48.28,51.24 R107.1
CSI_DATAP0_DVP_D1: length 13.8
  TOP w0.104: R100.1 53.05,51.21 53.05,49.45 TP18.1 53.05,48.86 53.05,48.5 53.31,48.24 53.31,48.06 53.06,47.81 53.06,47.64 53.18,47.52 53.35,47.52 53.61,47.77 53.78,47.77 54.07,47.48 54.07,39.74 U7.L1
CSI_DATAP1_DVP_D3: length 15.7
  TOP w0.104: R105.1 48.54,51.24 48.54,49.45 TP23.1 48.54,48.86 48.54,48.61 53.05,44.1 53.05,38.95 53.38,38.62 U7.M3
CSI_VCC08: length 5.4
  TOP w0.203: U7.N2 52.73,39.19 52.24,39.67 52.24,40.9 v1(52.03,41.11)
  BOTTOM w0.381: FB9.1 53.55,39 52.59,39.96 C146.1 C147.1 52.29,40.85 v1(52.03,41.11)
CSI_VCC18: length 5
  TOP w0.254: U7.K3 v1(54.35,38.07)
  BOTTOM w0.381: FB10.1 55.41,41.19 C145.1 55.42,40.27 C144.1 55.41,39.63 55.01,39.23 55.01,38.61 54.48,38.07 v1(54.35,38.07)
DDR_VREF: length 5.8
  TOP w0.254: U7.E5 v1(58.25,37.43)
  BOTTOM w0.381: R118.1 C42.2 57.55,39.85 R119.2 C43.1 58.25,40.04 v1(58.25,37.43)
DDRPLL_VCCA: length 3.8
  TOP w0.254: U7.B8 v1(60.2,34.83)
  BOTTOM w0.381: v1(60.2,34.83) 61.74,34.83 C133.1 C134.1 63.51,34.79 FB2.1
DDRVDD: length 8.7
  TOP w0.254: U7.F6 v1(57.6,36.78) U7.F5 ; U7.E11 v1(58.25,32.87) U7.E12 ; U7.F10 v1(57.6,34.18) U7.F9 ; U7.E7 v1(58.25,35.48) U7.E8 ; U7.F8 v1(57.6,35.48) U7.F7 ; U7.E10 v1(58.25,34.18) U7.E9 ; U7.E6 v1(58.25,36.78) ; U7.F11 v1(57.6,32.87) U7.F12
  BOTTOM w0.381: C44.1 57.7,38.1 C42.1 R118.2
  vias: v1(65.25,30.36) v1(65.53,29.89) v1(65.76,30.36) v1(66.1,29.92) v1(66.34,30.38) v1(66.61,29.92)
DVP_D0: length 37.4
  TOP w0.102: v1(60.4,58.44) 60.13,58.44 57.14,61.43 51.22,61.43 41.92,70.73 J10.11 ; R103.2 v1(53.78,50.07)
  BOTTOM w0.102: v1(60.4,58.44) 60.38,58.41 60.38,55.79 54.91,50.32 54.02,50.32 v1(53.78,50.07)
DVP_D1: length 40.6
  TOP w0.102: v1(60.39,58.97) 59.97,58.97 57.07,61.86 51.49,61.86 42.42,70.94 J10.12 ; R101.2 v1(52.59,50.07)
  BOTTOM w0.102: v1(60.39,58.97) 59.94,58.52 59.94,55.89 54.72,50.68 53.19,50.68 v1(52.59,50.07)
DVP_D2: length 39.8
  TOP w0.102: v1(58.91,60.79) 58.91,60.84 57.53,62.22 51.84,62.22 42.92,71.14 J10.13 ; R107.2 v1(47.82,50.1)
  BOTTOM w0.102: v1(47.82,50.1) 49.92,52.2 54.1,52.2 58.46,56.57 58.46,60.34 v1(58.91,60.79)
DVP_D3: length 41.8
  TOP w0.102: v1(59.47,60.76) 59.47,60.89 57.64,62.72 52.05,62.72 43.42,71.35 J10.14 ; R105.2 v1(49,50.1)
  BOTTOM w0.102: v1(49,50.1) 50.67,51.77 54.26,51.77 58.9,56.41 58.9,60.19 v1(59.47,60.76)
DVP_D4: length 41
  TOP w0.102: v1(60.03,60.3) 60.03,60.75 57.72,63.07 52.24,63.07 44.42,70.89 J10.16 ; R124.2 v1(50.16,50.08)
  BOTTOM w0.102: v1(50.16,50.08) 51.51,51.43 54.43,51.43 59.23,56.22 59.23,59.45 60.03,60.25 v1(60.03,60.3)
DVP_D5: length 37.5
  TOP w0.102: v1(60.38,59.87) 60.48,59.97 60.48,60.64 57.75,63.38 52.64,63.38 44.92,71.1 J10.17 ; R109.2 v1(51.34,50.08)
  BOTTOM w0.102: v1(51.34,50.08) 52.29,51.03 54.46,51.03 59.59,56.16 59.59,59.45 60.01,59.87 v1(60.38,59.87)
